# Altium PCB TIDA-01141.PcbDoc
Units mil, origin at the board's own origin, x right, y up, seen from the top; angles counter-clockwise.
Board outline 728.35 x 866.14 mil, 2 copper layers (Top Layer, Bottom Layer), stack 62 mil thick; 33 components, 14 nets, 69 pads, 28 vias.
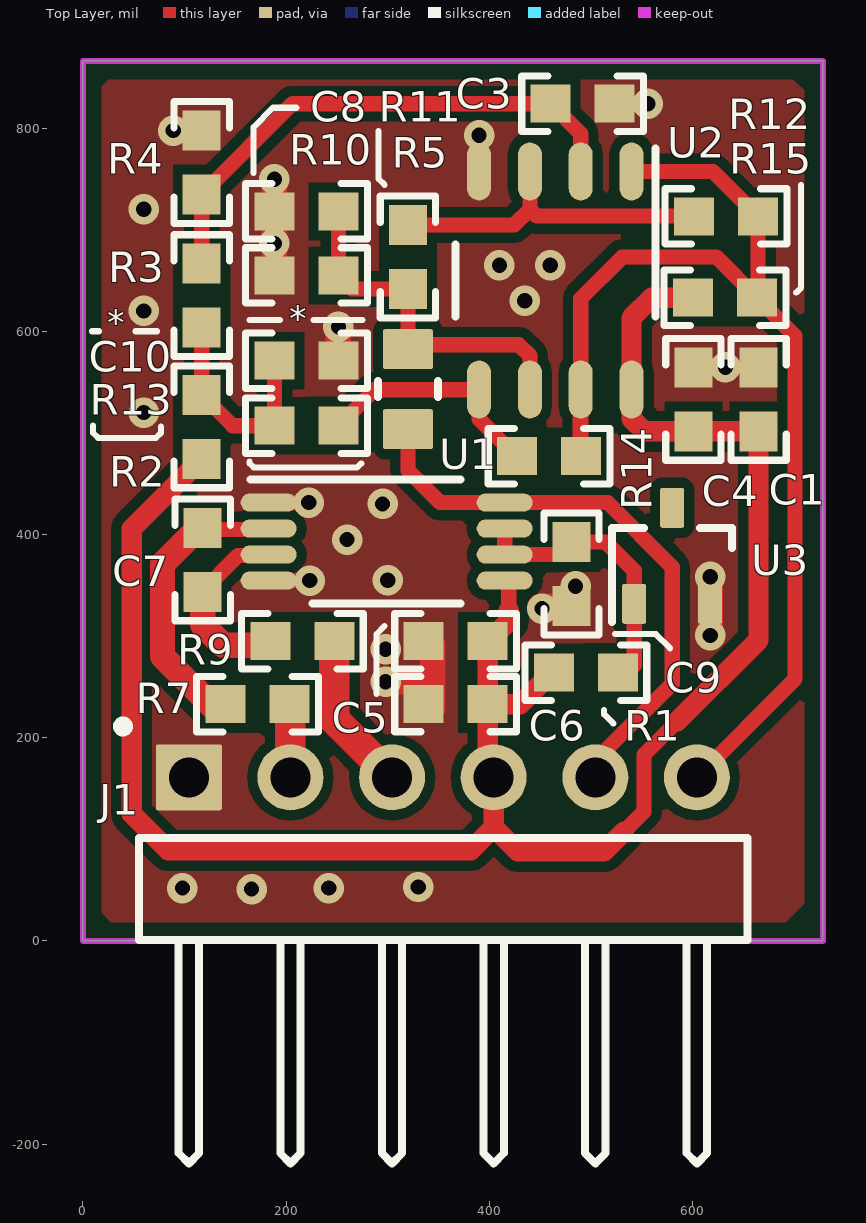
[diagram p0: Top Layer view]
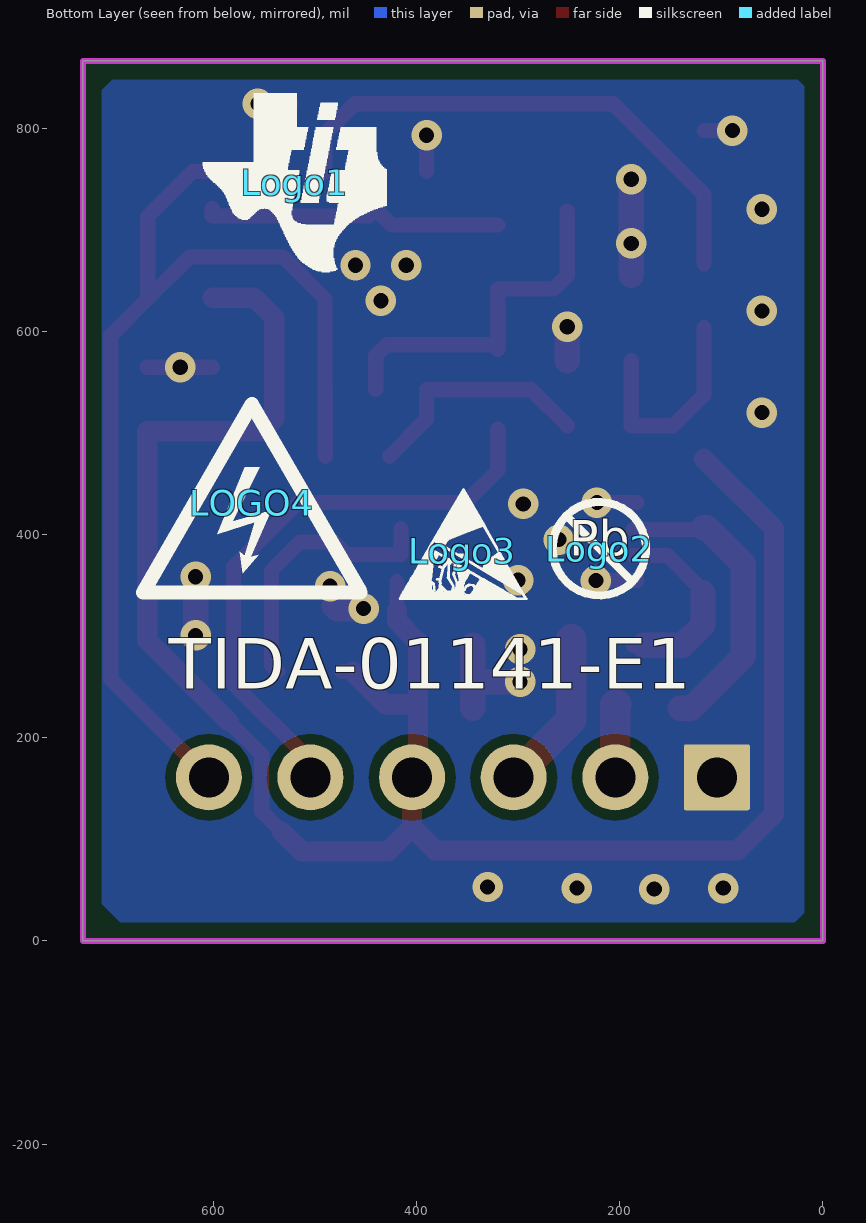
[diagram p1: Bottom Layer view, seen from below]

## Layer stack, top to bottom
Top Solder: solder mask 0.4, Solder Resist, Dk 3.5
Top Layer: signal copper 1.4
Dielectric1: core 59.2, FR-4 High Tg, Dk 4.8
Bottom Layer: signal copper 1.4
Bottom Solder: solder mask 0.4, Solder Resist, Dk 3.5

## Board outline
0,0 0,866.14 728.35,866.14 728.35,0

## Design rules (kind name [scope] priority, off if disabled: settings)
AcuteAngle [All] p1: minimum=4.50000000000000E+0001 checktracksonly=FALSE
AssemblyTestPointUsage [All] p1: valid=2
Clearance Clearance_Keepouts [((IsTrack Or IsArc) And Not InPoly) And IsFree and IsKeepOut vs ((IsTrack Or IsArc) And Not InPoly) And IsFree and IsKeepOut] p1: gap=15
Clearance Clearance_BoardEdge_MountingHoles [OnCopper and InComponentClass('Mounting Holes') vs IsKeepOut] p2: gap=40
Clearance Clearance_BoardEdge_Poly [OnCopper and InPoly vs IsKeepOut] p3: gap=15
Clearance Clearance_BoardEdge [OnCopper and Not InComponentClass('Logo') and not InComponentClass('FiducialMark') and not InRegion(1000,500,4000,800) and Not IsKeepout vs IsKeepOut] p4: gap=20 except(15: Track-Track)
Clearance Clearance_Poly [InPolygon] p5: gap=10
Clearance [All] p6: gap=7.87
ComponentClearance ComponentClearance_MountingHoles_FiducialMarks [InComponentClass('Mounting Holes') vs InComponentClass('FiducialMark')] p1: gap=50 collisioncheckmode=3 verticalgap=10 showdistances=FALSE
ComponentClearance ComponentClearance_Shunt [InComponentClass('Header') vs InComponentClass('Shunt')] p2: gap=0 collisioncheckmode=3 verticalgap=0 showdistances=FALSE
ComponentClearance ComponentClearance_Logo [InComponentClass('Logo')] p3: gap=50 collisioncheckmode=3 verticalgap=10 showdistances=FALSE
ComponentClearance ComponentClearance_ScrewToNut [(HasFootprint('NY PMS 440 0025 PH')) vs (HasFootprint('Keystone_1902C'))] p4: gap=5 collisioncheckmode=3 verticalgap=10 showdistances=FALSE
ComponentClearance ComponentClearance_MountingHoles [InComponentClass('Mounting Holes')] p5: gap=200 collisioncheckmode=3 verticalgap=100000 showdistances=FALSE
ComponentClearance ComponentClearance_SmallPassives [HasFootprint('0201*') or HasFootprint('0402*') or HasFootprint('0508') or HasFootprint('0603*') or HasFootprint('0612') or HasFootprint('0805*') or HasFootprint('0815*') or HasFootprint('0830*') or HasFootprint('1206*') or HasFootprint('1210*') or HasFootprint('1808*') or HasFootprint('1812*') or HasFootprint('1825*') or HasFootprint('2010*') or HasFootprint('2220*') or HasFootprint('2225*') or HasFootprint('2512*') or HasFootprint('2728*') or HasFootprint('3518*') vs HasFootprint('0201*') or HasFootprint('0402*') or HasFootprint('0508') or HasFootprint('0603*') or HasFootprint('0612') or HasFootprint('0805*') or HasFootprint('0815*') or HasFootprint('0830*') or HasFootprint('1206*') or HasFootprint('1210*') or HasFootprint('1808*') or HasFootprint('1812*') or HasFootprint('1825*') or HasFootprint('2010*') or HasFootprint('2220*') or HasFootprint('2225*') or HasFootprint('2512*') or HasFootprint('2728*') or HasFootprint('3518*')] p6: gap=20 collisioncheckmode=3 verticalgap=10 showdistances=FALSE
ComponentClearance ComponentClearance_THtoSMT [IsThruComponent vs IsSMTComponent] p7: gap=20 collisioncheckmode=3 verticalgap=20 showdistances=FALSE
ComponentClearance ComponentClearance_THtoTH [IsThruComponent vs IsThruComponent] p8: gap=10 collisioncheckmode=3 verticalgap=10 showdistances=FALSE
ComponentClearance [All] p9: gap=20 collisioncheckmode=3 verticalgap=10 showdistances=FALSE
DiffPairsRouting [All] p1: maxlimit=100 minlimit=10 mostfreqgap=10 toplayer_minwidth=15 toplayer_maxwidth=15 toplayer_prefwidth=15 bottomlayer_minwidth=15 bottomlayer_maxwidth=15 bottomlayer_prefwidth=15 maxuncoupledlength=1000
FabricationTestPointUsage TestPointUsage [All] p1: valid=2 allowmultiple=FALSE
FabricationTestpoint Testpoint [All] p1: side=3 testpointundercomponent=TRUE minsize=40 maxsize=100 preferedsize=60 minholesize=0 maxholesize=40 preferedholesize=32 testpointgrid=1 allowsidetop=TRUE allowsidebottom=TRUE usegrid=TRUE gridtolerance=0.01
FanoutControl Fanout_LCC [IsLCC] p1: bgadir=Out bgaviamode=Centered fanoutstyle=Auto fanoutdirection=Alternating viagrid=1 // Fanout_LCC (Default Rule)
FanoutControl Fanout_BGA [IsBGA] p2: bgadir=Out bgaviamode=Centered fanoutstyle=Auto fanoutdirection=Alternating viagrid=1 // Fanout_BGA (Default Rule)
FanoutControl Fanout_Default [All] p4: bgadir=Out bgaviamode=Centered fanoutstyle=Auto fanoutdirection=Alternating viagrid=1 // Fanout_Default (Default Rule)
FanoutControl Fanout_Small [(CompPinCount < 5)] p5: bgadir=Out bgaviamode=Centered fanoutstyle=Auto fanoutdirection=OutThenIn viagrid=1 // Fanout_Small (Default Rule)
HoleSize [All] p1: absolutevalues=TRUE maxlimit=251 minlimit=8 maxpercent=80.000 minpercent=20.000
MinimumAnnularRing MinimumAnnularRing_ThermalPadVias [IsVia and InAnyComponent] p1: minimumring=5.91
MinimumAnnularRing [All] p2: minimumring=6
MinimumSolderMaskSliver MinimumSolderMaskSliver_Logo [InComponentClass('Logo') vs InComponentClass('Logo')] p1: minsoldermaskwidth=0.7
MinimumSolderMaskSliver [All] p2: minsoldermaskwidth=3.94
PlaneConnect [All] p1: planeconnectstyle=Relief reliefexpansion=10 reliefentries=4 reliefconductorwidth=10 reliefairgap=10
PolygonConnect [All] p1: connectstyle=Direct reliefconductorwidth=10 reliefentries=4 polygonreliefangle="90 Angle" airgapwidth=10
RoutingVias ThermalPadVias [IsVia and InAnyComponent] p1: holewidth=7.87 width=19.68 viastyle="Through Hole" minholewidth=7.87 minwidth=19.68 maxholewidth=12.99 maxwidth=23.62
RoutingVias [All] p2: holewidth=12 width=24 viastyle="Through Hole" minholewidth=7.87 minwidth=26 maxholewidth=40 maxwidth=65
SilkToBoardRegionClearance [Not ((IsComment or IsDesignator) And (Hide <> 'False')) and not InRegion(1000,500,4000,800)] p1:
SilkToSilkClearance SilkToSilkClearance_Pb-FreeLogo [(HasFootprint('Pb-Free_Overlay_Medium') OR HasFootprint('Pb-Free_Overlay_Small')) vs (HasFootprint('Pb-Free_Overlay_Medium') OR HasFootprint('Pb-Free_Overlay_Small'))] p1: silktosilkclearance=0
SilkToSilkClearance [All] p2: silktosilkclearance=4
SilkToSolderMaskClearance "Silk to Solder Mask Opening" [All] p1: minsilkscreentomaskgap=4 clearancetoexposedcopper=FALSE
SolderMaskExpansion [All] p1: expansion=1.97
UnpouredPolygon [All] p1: allowunpoured=FALSE
Width [All] p1: maxlimit=60 minlimit=6 preferedwidth=20 checkconnectedcopper=TRUE
14 further rules are at their usual default settings.

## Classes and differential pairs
component class TIDA-01141_Sheet1: C1 C3 C4 C5 C6 C7 C8 C9 C10 J1 R1 R2 R3 R4 R5 R7 R9 R10 R11 R12 R13 R14 R15 U1 U2 U3
component class AssemblyNote: ZZ1 ZZ2 ZZ3
component class TIDA-01141_Hardware: Logo1 Logo2 Logo3 LOGO4 ZZ1 ZZ2 ZZ3
component class Logo: Logo1

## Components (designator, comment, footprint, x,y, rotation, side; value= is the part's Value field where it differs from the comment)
C1 "C0603C105K8PACTU" 0603 665,533 r270 top
C3 "06031C102JAT2A" 0603 492,824 r180 top
C4 "GRM188R71C104KA01D" 0603 601,533 r90 top
C5 "GRM188R71C104KA01D" 0603 367,295 r180 top
C6 "C0603C105K8PACTU" 0603 367,233 r0 top
C7 "06031C103JAT2A" 0603 118,375 r270 top
C8 "06031C102JAT2A" 0603 220,718 r0 top
C9 "06031C102JAT2A" 0603 481,361 r90 top
C10 "06031C102JAT2A" 0603 220,571 r180 top
J1 "TSW-106-08-G-S-RA" TSW-106-08-G-S-RA 354.33,161 r0 top locked
Logo1 "Texas Instruments" TI_Symbol_Overlay_Small 520,746 r180 bottom
Logo2 "Pb-Free Symbol" Pb-Free_Overlay_Small 220,386 r180 bottom
Logo3 "ESD Susceptible" ESD_Overlay_Small 355,384 r180 bottom
LOGO4 "DANGER HIGH VOLTAGE" IEC_HighVoltage_Small 562,431 r180 bottom
R1 "RC0603FR-075K11L" 0603 495,264 r180 top
R2 "CRCW060324K3FKEA" 0603 117,506 r270 top
R3 "CRCW060314K3FKEA" 0603 117,635 r270 top
R4 "CRCW06034K12FKEA" 0603 117,766 r270 top
R5 "CRCW08051K00FKEA" 0805_HV1 320,543 r90 top
R7 "CRCW06034R75FKEA" 0603 172,233 r180 top
R9 "CRCW06034R75FKEA" 0603 216,295 r180 top
R10 "CRCW06031K00FKEA" 0603 220,655 r180 top
R11 "CRCW060310K0FKEA" 0603 320,673 r90 top
R12 "CRCW06033M32FKEA" 0603 633,713 r0 top
R13 "CRCW060310K0FKEA" 0603 220,507 r180 top
R14 "CRCW06033M32FKEA" 0603 459,477 r0 top
R15 "CRCW06033K32FKEA" 0603 632,633 r180 top
U1 "INA240A2PW" PW0008A_N 299,393 r0 top
U2 "LM393AD" D0008A_N 465,650 r270 top
U3 "LM4040D30IDBZR" DBZ0003A_N 580,379 r90 top
ZZ1 "These assemblies are ESD sensitive, ESD precautions shall be observed." AssemblyNote -85,1683.6 r0 top
ZZ2 "These assemblies must be clean and free from flux and all contaminants. Use of no clean flux is not acceptable." AssemblyNote -85,1595.05 r0 top
ZZ3 "These assemblies must comply with workmanship standards IPC-A-610 Class 2, unless otherwise specified." AssemblyNote -85,1506.49 r0 top

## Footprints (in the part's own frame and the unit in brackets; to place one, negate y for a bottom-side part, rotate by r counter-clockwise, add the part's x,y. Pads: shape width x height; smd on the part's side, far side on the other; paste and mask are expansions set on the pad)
0603 [mm] "0603 from SM-752 data"
  rect 1x0.95 smd: 1(-0.8,0) 2(0.8,0)
  silkscreen extent -1.52,-0.69 1.52,0.69, body extent -0.87,-0.47 0.87,0.47, height 1
0805_HV1 [mm] "Custom footprint based on analyzing multiple manufacturer recommendations"
  rrect10% 1x1.25 smd: 1(-1,0) 2(1,0)
  silkscreen extent -0.2,-0.75 0.2,0.75, body extent -1.1,-0.72 1.1,0.73, height 1.45
AssemblyNote [mil] "Assembly Note"
D0008A_N [mm] "SOIC, 8-Leads, Body 4.9x3.9mm, Pitch 1.27mm, IPC Medium Density"
  oval 1.45x0.6 smd: 1(-2.725,1.905) 2(-2.725,0.635) 3(-2.725,-0.635) 4(-2.725,-1.905) 5(2.725,-1.905) 6(2.725,-0.635) 7(2.725,0.635) 8(2.725,1.905)
  silkscreen extent -3.3,-2.5 0.9,2.5, body extent -3,-2.45 3,2.45, height 1.63
DBZ0003A_N [mm] "SOT23, 3-Leads, Body 2.9x1.3mm, Pitch 0.95mm, Lead Span 2.4mm, IPC Medium Density"
  rrect17% 1x0.6 smd: 1(-1.2,0.95) 2(-1.2,-0.95) 3(1.2,0)
  silkscreen extent -1.65,-1.5 0.7,1.5, body extent -1.26,-1.46 1.26,1.46, height 0.98
ESD_Overlay_Small [mil]
  silkscreen extent -62,-48 64,61
IEC_HighVoltage_Small [mil]
  silkscreen extent -107,-88 107,97
Pb-Free_Overlay_Small [mil]
  silkscreen extent -46,-46 46,46
PW0008A_N [mm] "TSOP, 8-Leads, Body 3x4.4mm, Pitch 0.65mm, IPC Medium Density"
  oval 1.4x0.45 smd: 1(-2.95,0.975) 2(-2.95,0.325) 3(-2.95,-0.325) 4(-2.95,-0.975) 5(2.95,-0.975) 6(2.95,-0.325) 7(2.95,0.325) 8(2.95,0.975)
  silkscreen extent -3.4,-1.55 1.85,1.55, body extent -3.21,-1.5 3.21,1.5, height 1.2
TI_Symbol_Overlay_Small [mil]
  silkscreen extent -90,-88 91,88
TSW-106-08-G-S-RA [mm] "Samtec Right Angle Header"
  rrect6% 1.65x1.65 hole 1: 1(-6.35,0)
  round 1.65 hole 1: 2(-3.81,0) 3(-1.27,0) 4(1.27,0) 5(3.81,0) 6(6.35,0)
  silkscreen extent -8.12,-9.65 7.62,1.39, body extent -7.62,-9.91 7.62,0.32, height 3.05

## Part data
C1 C6: "CAP, CERM, 1 µF, 10 V, +/- 10%, X5R, 0603"
C3 C8 C9 C10: "CAP, CERM, 1000 pF, 100 V, +/- 5%, X7R, 0603"
C4 C5: "CAP, CERM, 0.1 µF, 16 V, +/- 10%, X7R, 0603"
C7: "CAP, CERM, 0.01 µF, 100 V, +/- 5%, X7R, 0603"
J1: "Header, 100mil, 6x1, Gold, R/A, TH"
Logo1: library part TI_Logo, "Texas Instrument Corporate Signature"
Logo2: library part Pb-Free
Logo3: library part ESD_Susceptible, "ESD Susceptible Symbol"
LOGO4: library part IEC_HighVoltage, "IEC 61010-1 High Voltage Warning"
R1: "RES, 5.11 k, 1%, 0.1 W, 0603"
R2: "RES, 24.3 k, 1%, 0.1 W, 0603"
R3: "RES, 14.3 k, 1%, 0.1 W, 0603"
R4: "RES, 4.12 k, 1%, 0.1 W, 0603"
R5: "RES, 1.00 k, 1%, 0.125 W, 0805"
R7 R9: "RES, 4.75, 1%, 0.1 W, 0603"
R10: "RES, 1.00 k, 1%, 0.1 W, 0603"
R11 R13: "RES, 10.0 k, 1%, 0.1 W, 0603"
R12 R14: "RES, 3.32 M, 1%, 0.1 W, 0603"
R15: "RES, 3.32 k, 1%, 0.1 W, 0603"
U1: "Wide Common-Mode Range, Voltage Output, High or Low-Side Bi-Directional Zero-Drift Current Shunt Monitor, PW0008A"
U2: "Dual Comparator, D0008A"
U3: "Precision Micropower Shunt Voltage Reference, 1% accuracy, 3 V, 15 ppm / degC, 15 mA, -40 to 85 degC, 3-pin SOT-23 (DBZ), Green (RoHS & no Sb/Br)"
ZZ1 ZZ2 ZZ3: library part AssemblyNote

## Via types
v1: diameter 30, hole 15, Top Layer to Bottom Layer, tented both sides, 28 vias

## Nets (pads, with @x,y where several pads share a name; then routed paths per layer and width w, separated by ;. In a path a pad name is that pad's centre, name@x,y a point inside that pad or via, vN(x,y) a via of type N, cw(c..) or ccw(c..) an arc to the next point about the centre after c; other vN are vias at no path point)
HTV: C10.2 R2.1 R3.2 R13.2 | length 214.1
  Top Layer w15: R3.2 R2.1 147.5,507 R13.2 C10.2
IBAT_ALERT: J1.6 R12.2 R14.2 R15.1 U2.1 U2.7 | length 1194.7
  Top Layer w15: U2.1@540,773 U2.1 620.21,757.28 R12.2 664.5,634 R15.1 ; J1.6 701,257.67 701,595.5 R15.1 ; U2.7 489.5,542.21 489.5,477 490,477.5 U2.7 ; U2.7 490,632 531,673 623.5,673 R15.1
IBAT_HS: J1.5 R5.1 U1.8 | length 578.3
  Top Layer w15: R5.1 320,463 351.61,431.39 U1.8 516.61,431.39 580,368 580,253 504.33,177.33 J1.5
IBAT_HS+: J1.2 R7.1 | length 72.3
  Top Layer w30: R7.1 204.33,232.17 J1.2
IBAT_HS-: J1.3 R9.1 | length 159.5
  Top Layer w30: R9.1@247.5,297 R9.1 247.5,217.83 J1.3
LTV: C3.2 R3.1 R4.2 U2.2 | length 527.5
  Top Layer w15: R3.1 R4.2 206.5,824 C3.2 490,794.5 U2.2
LV_AUX_3.3V: C1.2 C4.1 C5.1 C6.2 J1.4 R1.2 R2.2 R15.2 U1.5 U2.8 | length 1993.9
  Top Layer w15: 419.14,325 U1.5@419.14,353.61 ; R1.2@462.5,265 R1.2@473.5,265 ; 532.59,107.59 552.18,127.18 552.18,183.18 585,216
  Top Layer w20: R2.2 48,405.5 48,125 84,89 381.66,89 404.33,111.67 ; C5.1 C5.1@398.5,294 ; 419.13,325 419.13,314.63 C5.1@398.5,294 ; R1.2@462.5,265 430.5,233 C6.2 ; 532.59,107.59 513,88 428,88 404.33,111.67 ; 585,216 665,296 C1.2 C4.1 552.5,501.5 540,514 U2.8 540,613.12 559.88,633 R15.2 ; C6.2 398.5,166.83 J1.4 404.33,111.67 ; C6.2 C5.1@398.5,294
NetC7_1: C7.1 R7.2 U1.2 | length 371.6
  Top Layer w15: 78,291.5 78,355 ; C7.1 114,402.5 118,402.5 120.3,404.8 U1.2@186.86,404.8
  Top Layer w25: C7.1 113.79,406.5 78.37,371.08 78.37,280 129.37,229 R7.2@140.5,229
NetC7_2: C7.2 R9.2 U1.3 | length 195.4
  Top Layer w15: C7.2 118,342.5 117,343.5 152.7,379.2 U1.3@186.86,379.2 ; R9.2@176.5,291 R9.2@186.5,291
  Top Layer w25: C7.2@118,342.5 118,311 138,291 R9.2@176.5,291
NetC8_2: C8.2 R5.2 R10.1 R11.1 U2.6 | length 355.7
  Top Layer w15: C8.2 251.5,704 R10.1 264.99,641.5 R11.1 R5.2 324.26,586.63 429.37,586.63 440,576 U2.6
NetR11_2: R11.2 R12.1 U2.3 | length 334.6
  Top Layer w15: R11.2 424.5,704.5 440,720 ; U2.3 440,720 ; R12.1@601,720.5 601,713.37 446.63,713.37 440,720
NetR13_1: R13.1 R14.1 U2.5 | length 234.1
  Top Layer w15: R13.1 286.81,542.31 389.59,542.31 U2.5 390,513.5 R14.1@426.5,477
SGND: C1.1 C3.1 C4.2 C5.2 C6.1 C8.1 C9.1 C10.1 J1.1 R4.1 R10.2 U1.1 U1.4 U2.4 U3.2 | length 604.7
  Top Layer w15: v1@88.46,797 v1(88.95,797.5) R4.1 ; U1.4 v1(223.39,354.61) ; U1.1 v1(222.39,431.39) ; U2.4 v1(390,793) v1@390,796 ; C3.1 v1(556,824) ; C4.2 v1(632.5,564.5) C1.1
  Top Layer w25: R10.2 v1(188.5,686.5) C8.1 v1(188.5,749.5) ; C10.1 v1(251.5,604.5) ; v1(298,255) 339.5,255 344.5,260 ; C6.1@344.5,229 C5.2@344.5,291 ; v1(617.4,300.6) U3.2 v1(617.4,358.4) ; v1@450.07,328.93 v1(452,327) 478.5,327 C9.1 450.07,329.5 v1@450.07,328.93
  other v1: 166,51 98,52 242,52 330,53 298,287 485,349 300,355 260,395 295,430 60,520 60,620 435,630 410,665 460,665 60,720
VREF: C9.2 R1.1 U1.6 U1.7 U3.1 | length 271.7
  Top Layer w15: U1.7 U1.6 468.71,380.2 C9.2 514.5,392.5 542.6,364.4 U3.1 542.6,271.1 R1.1@536.5,265
pads on no net: U3.3

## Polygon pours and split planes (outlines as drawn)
SGND on Top Layer "M9 Title Sheet-No Net" (solid, remove dead copper, pour order 4): 0,806 0,46 46,0 673.35,0 728.35,55 728.35,818.65 679,868 45,868 0,823
SGND on Bottom Layer "M9 Title Sheet-No Net" (solid, remove dead copper, pour order 3): 0,806 0,46 46,0 673.35,0 728.35,55 728.35,818.65 679,868 45,868 0,823

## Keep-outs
Keep-Out Layer:
  lines w6: 0,0 728.35,0 728.35,866.14 0,866.14 0,0 ; 708.66,0 708.66,0
  lines w10: 4730,3149.49 cw(c4730,3144.49) 4735,3144.49 ccw(c4730,3144.49) 4730,3149.49
  text ".Layer_Name" at 357,-1164.01 h60

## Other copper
Top Layer:
  text ".Layer_Name" at 357,-1164.01 h60
Bottom Layer:
  text ".Layer_Name" at 357,-1164.01 h60

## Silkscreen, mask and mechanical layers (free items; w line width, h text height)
Top Overlay:
  lines w6: 9,600 16,600 ; 10,507 10,500 15,495 72,495 77,500 77,506 ; 52,600 73,600 ; 164,472 164,470 168,466 270,466 274,470 ; 164,611 194,611 ; 168,756 168,801 187,820 210,820 ; 227,611 275,611 ; 289,243 289,302 297,310 ; 291,797 291,750 297,744 ; 513,227 513,223 522,214 ; 524,302 564,302 578,288 ; 702,638 707,643 707,744
  text "*" at 203,600 h25
  text "*" at 24,596 h25
  text ".Layer_Name" at 357,-1164.01 h60
Bottom Overlay:
  text "TIDA-01141-E1" at 644,248 h50
  text ".Layer_Name" at 357,-1164.01 h60
Top Paste:
  text ".Layer_Name" at 357,-1164.01 h60
Bottom Paste:
  text ".Layer_Name" at 357,-1164.01 h60
Top Solder:
  text ".Layer_Name" at 357,-1164.01 h60
  text ".Layer_Name" at 357,-1164.01 h60
Bottom Solder:
  text ".Layer_Name" at 357,-1164.01 h60
Drill Guide:
  text ".Layer_Name" at 357,-1164.01 h60
M1 Board Outline:
  the board outline again, w10
M2 Board Dimensions:
  rectangle: -95,-705.51 280,-580.51
  rectangle: -220,-580.51 -95,-455.51
  lines w7: -220,-580.51 780,-580.51 ; -95,-705.51 -95,-455.51 ; 30,-705.51 30,-455.51 ; 280,-705.51 280,-455.51 ; 530,-705.51 530,-455.51 ; -220,-705.51 -220,-455.51 780,-455.51 780,-705.51 -220,-705.51
M3 3D STEP Top:
  text ".Layer_Name" at 357,-1164.01 h60
M4 3D STEP Bottom:
  text ".Layer_Name" at 357,-1164.01 h60
M5 Assembly Top:
  lines w10: -512,-1235.68 6088,-1235.68 ; -512,-1032.35 6090,-1032.35 ; -512,-829.01 -512,-1439.01 3493,-1439.01 6090,-1439.01 6090,-829.01 -511.5,-829.01 -511.5,-1439.01 1064,-1439.01 ; 1953,-1439.01 1953,-829.01 ; 3220,-1032.35 3220,-829.01 ; 4060,-1032.35 4060,-829.01 ; 4682,-1445.51 4682,-1242.68
  text "COMPONENTS MARKED 'DNP' SHOULD NOT BE POPULATED." at 933.5,-624.01 h60
  text "ASSEMBLY VARIANT:" at 933,-739.51 h60
  text ".VariantName" at 1969,-739.51 h60
  text "PCB VIEWED FROM TOP SIDE" at -448.5,-961.18 h60
  text "BOARD #:" at 2028,-961.18 h60
  text ".PRJ_Number" at 2573.5,-961.18 h60
  text "REV:" at 3418,-961.18 h60
  text ".PCB_Rev" at 3709.5,-961.18 h60
  text "SVN REV:" at 4256,-961.18 h60
  text ".VersionControl_RevNumber" at 4762,-961.18 h60
  text ".LAyer_Name" at 317,-1163 h60
  text "TID #:" at 2028,-1164.51 h60
  text ".TID" at 2573.5,-1164.51 h60
  text "PLOT NAME =" at -448.5,-1369.85 h60
  text ".plot_File_Name" at 357,-1369.85 h60
  text "GENERATED    :" at 2030,-1369.85 h60
  text ".Print_Date" at 2899.5,-1369.85 h60
  text ".Print_Time" at 3628.5,-1369.85 h60
  text "TEXAS INSTRUMENTS" at 4893,-1369.85 h60
M6 Assembly Bottom:
  lines w10: -512.5,-1032.85 6089.5,-1032.85 ; -510.5,-1236.18 6089.5,-1236.18 ; 895.5,-1446.01 895.5,-1243.18 ; 1517.5,-1032.85 1517.5,-829.51 ; 2357.5,-1032.85 2357.5,-829.51 ; 3624.5,-1439.51 3624.5,-829.51 ; 4513.5,-1439.51 6089,-1439.51 6089,-829.51 -512.5,-829.51 -512.5,-1439.51 2084.5,-1439.51 6089.5,-1439.51 6089.5,-829.51
  text "COMPONENTS MARKED 'DNP' SHOULD NOT BE POPULATED." at 5882,-623.51 h60
  text ".VariantName" at 4838,-739.51 h60
  text "ASSEMBLY VARIANT:" at 5877,-739.51 h60
  text ".VersionControl_RevNumber" at 815.5,-961.68 h60
  text "SVN REV:" at 1321.5,-961.68 h60
  text ".PCB_Rev" at 1868,-961.68 h60
  text "REV:" at 2159.5,-961.68 h60
  text ".PRJ_Number" at 3004,-961.68 h60
  text "BOARD #:" at 3549.5,-961.68 h60
  text "PCB VIEWED FROM BOTTOM SIDE" at 6026,-961.68 h60
  text ".LAyer_Name" at 5043,-1160 h60
  text ".TID" at 3004,-1165.01 h60
  text "TID #:" at 3549.5,-1165.01 h60
  text "TEXAS INSTRUMENTS" at 684.5,-1370.35 h60
  text ".Print_Time" at 1949,-1370.35 h60
  text ".Print_Date" at 2678,-1370.35 h60
  text "GENERATED    :" at 3547.5,-1370.35 h60
  text ".plot_File_Name" at 5220.5,-1370.35 h60
  text "PLOT NAME =" at 6026,-1370.35 h60
M9 Title Sheet:
  drawing of 57 lines, arcs and shapes, not listed
  text "1" at 519.84,7730.99 h70
  text "2" at 3015.5,7730.99 h70
  text "3" at 5504.84,7730.99 h70
  text "4" at 8011.51,7730.99 h70
  text "5" at 10510.5,7730.99 h70
  text "6" at 13015.5,7730.99 h70
  text "A" at -636.5,6587.99 h70
  text "A" at 14163.5,6587.99 h70
  text "B" at -636.5,4207.99 h70
  text "B" at 14163.5,4207.99 h70
  text "C" at -636.5,1832.99 h70
  text "C" at 14163.5,1832.99 h70
  text "PROJECT TITLE:" at 11123.5,-28.01 h45
  text ".PRJ_Title" at 11173.5,-161.34 h70
  text "DESIGNED FOR:" at 11123.5,-329.01 h45
  text ".PRJ_Customer" at 11173.5,-469.01 h70
  text "D" at -636.5,-537.01 h70
  text "D" at 14163.5,-537.01 h70
  text "FILE NAME:" at 11123.5,-629.01 h45
  text ".PCB_File_Name_No_Path" at 11173.5,-749.01 h70
  text "Texas Instruments (TI) and/or its licensors do not warrant the accuracy or completeness of this specification" at 6154,-910.85 h45
  text "ENGINEER:" at 11123.5,-919.01 h45
  text "LAYOUT BY:" at 12628.5,-919.01 h45
  text "or any information contained therein. TI and/or its licensors do not warrant that this design will meet" at 6109.01,-1023.52 h45
  text ".PRJ_Engineer" at 11173.5,-1074 h70
  text ".PCB_Layout" at 12679,-1074 h70
  text "the specifications, will be suitable for your application or fit for any particular purpose, or will operate in" at 6109.01,-1136.18 h45
  text "ALTIUM DESIGNER VERSION:" at 12628.5,-1229.01 h45
  text "an implementation. TI and/or its licensors do not warrant that the design is production worthy. You should" at 6109.01,-1248.85 h45
  text "completely validate and test your design implementation to confirm the system functionality for your application." at 6154,-1361.51 h45
  text ".print_Scale" at 11173.5,-1362.34 h70
  text ".Application_BuildNumber" at 12679,-1362.34 h70
  text "1" at 519.84,-1569.01 h70
  text "2" at 3015.5,-1569.01 h70
  text "3" at 5504.84,-1569.01 h70
  text "4" at 8011.51,-1569.01 h70
  text "5" at 10510.5,-1569.01 h70
  text "6" at 13015.5,-1569.01 h70
M10 Fab Notes:
  drawing of 191 lines, arcs and shapes, not listed
  text "DESIGN INFORMATION" at 12166.52,6384.49 h60
  text "(REFER ALSO ARRAY/PANEL PROFILING INFORMATION)" at 11804.96,6222.77 h60
  text "BOARD SIZE" at 11118.96,6218.49 h60
  text "X" at 12086.96,6090.67 h60
  text "22MM" at 12322.5,6083.49 h60
  text "18.5MM" at 11581,6080 h60
  text "Number of Layers :" at 11536.96,5983.49 h60
  text "2" at 12631.77,5973.49 h60
  text "MIN. TRACK WIDTH:" at 11536.96,5844.49 h60
  text "15" at 12606.5,5844.89 h60
  text "MIL" at 12787.96,5844.49 h60
  text "MIN. CLEARANCE:" at 11536.96,5712.49 h60
  text "7.874" at 12475,5709 h60
  text "MIL" at 12805.5,5685.89 h60
  text "MIN. VIA PAD SIZE:" at 11536.96,5580.49 h60
  text "30" at 12617.5,5580.89 h60
  text "MIL" at 12805.5,5557.89 h60
  text "0.19mm (7.5MIL)" at 12231.96,5438.78 h60
  text "EXTERNAL" at 12968.5,5438.89 h60
  text "MINIMUM ANNULAR RING" at 11207.73,5434.49 h60
  text "PER" at 11407.73,5316.49 h60
  text "IPC-D-275 CLASS 2 LEVEL C" at 11627.73,5316.49 h60
  text "MIL, HOLES" at 13115.96,5204.2 h60
  text "+/-" at 12723.5,5203.49 h60
  text "+/-" at 13577.5,5203.49 h60
  text "REGISTRATION TOLERANCES:" at 11207.73,5198.49 h60
  text "METAL" at 12407.5,5198.49 h60
  text "5" at 12983.7,5198.49 h60
  text "3" at 13816.7,5198.49 h60
  text "MIL" at 13932.96,5198.49 h60
  text "IMPEDENCE CONTROLLED BOARD:NO" at 11240.5,5049.49 h60
  text "MATERIAL:" at 11116.96,4826.03 h60
  text "FR-4 High Tg" at 12103.4,4685.7 h60
  text "FR-408" at 11537.96,4677.13 h60
  text "OTHER" at 13025.96,4677.13 h60
  text "X" at 11941.5,4675.49 h60
  text "THICKNESS:" at 11118.5,4520.49 h60
  text "63 MIL (1.6mm) +/-10%" at 11777.5,4515.49 h60
  text "OTHER" at 13142.96,4510.13 h60
  text "X" at 11642.5,4507.49 h60
  text "TOLERANCE:" at 11191.73,4352.13 h60
  text "X" at 12031.03,4352.13 h60
  text "ANSI IPC-6012 TYPE 3 CLASS 2" at 12217.98,4352.13 h60
  text "OTHER +/-" at 12217.96,4196.13 h60
  text "BOW & TWIST:" at 11191.73,4039.13 h60
  text "X" at 12031.03,4039.13 h60
  text "ANSI IPC-6012 TYPE 3 CLASS 2" at 12217.98,4039.13 h60
  text "OTHER +/-" at 12217.96,3880.62 h60
  text "DRILLING:" at 11116.96,3742.13 h60
  text "REFERENCE:" at 11191.73,3625.13 h60
  text "X" at 11839.96,3625.13 h60
  text "AS SHOWN" at 12026.96,3625.13 h60
  text "X" at 12740.96,3625.13 h60
  text "NC_DRILL FILES" at 12877.96,3625.13 h60
  text "PTH MIN COPPER THICKNESS:" at 11191.73,3467.13 h60
  text "X" at 12541.96,3467.13 h60
  text "1MIL" at 12678.96,3467.13 h60
  text "OTHER" at 13175.96,3467.13 h60
  text "BOARD FINISH:" at 11116.96,3308.13 h60
  text "SILKSCREEN:" at 11272.18,3190.13 h60
  text "X" at 12220.96,3190.13 h60
  text "TOP" at 12346.96,3190.13 h60
  text "X" at 12730.96,3190.13 h60
  text "BOTTOM" at 12857.96,3190.13 h60
  text "SILKSCREEN COLOR:" at 11272.18,3023.13 h60
  text "X" at 12219.92,3023.13 h60
  text "WHITE" at 12346.96,3023.13 h60
  text "OTHER" at 12857.96,3023.13 h60
  text "SOLDER RESIST COLOR:" at 11272.18,2853.13 h60
  text "X" at 11839.92,2693.93 h60
  text "GREEN" at 11966.96,2693.93 h60
  text "BLUE" at 12557.96,2693.93 h60
  text "OTHER" at 13095.96,2693.93 h60
  text "IMMERSION GOLD (ENIG)" at 12177.96,2505.41 h60
  text "ENEPIG" at 13515.5,2502.13 h60
  text "SURFACE FINISH:" at 11116.96,2501.13 h60
  text "X" at 11991.01,2501.13 h60
  text "IMM. TIN/SILVER OR EQUIV" at 11446.5,2344.13 h60
  text "OTHER" at 12877.96,2344.13 h60
  text "ARRAY/PANEL:" at 11116.96,2165.13 h60
  text "CUT AND TRIM PER MECH LAYER 1" at 12177.96,2160.84 h60
  text "N.C. ROUTE" at 12177.96,2009.13 h60
  text "X" at 12856.96,2009.13 h60
  text "V. SCORE" at 13043.96,2009.13 h60
  text "CERTIFICATION:" at 11116.96,1872.13 h60
  text "MATERIALS AND WORKMANSHIP FOR ALL PCBS" at 11841.96,1872.13 h60
  text "TO MEET OR EXCEED THE REQUIREMENTS OF:" at 11841.96,1774.13 h60
  text "X" at 11468.46,1637.62 h60
  text "ANSI IPC-A-600F CLASS ->" at 11607.46,1637.62 h60
  text "X" at 13246.52,1637.62 h60
  text "2" at 13365.46,1637.62 h60
  text "1" at 13050.46,1636.13 h60
  text "3" at 13719.46,1636.13 h60
  text "X" at 11470.52,1478.13 h60
  text "UL 94V-0" at 11607.46,1478.13 h60
  text "X" at 12282.52,1478.13 h60
  text "RoHS" at 12419.46,1478.13 h60
  text "OTHER" at 13063.86,1478.13 h60
  text "PER ORDER" at 13460.92,1478.13 h60
  text "ADDITIONAL REQUIREMENTS:" at 11116.96,1337.13 h60
  text "MICROSECTION:" at 11191.73,1222.13 h60
  text "YES" at 12097.46,1222.13 h60
  text "REQUIRED" at 12958.96,1065.98 h60
  text "BARE BOARD ELEC. TEST:" at 11191.73,1063.13 h60
  text "NONE" at 12497.46,1063.13 h60
  text "X" at 12831.96,1063.13 h60
  text "PER ORDER" at 13550.96,1063.13 h60
  text "MANUFACTURER'S UL:" at 11191.73,906.13 h60
  text "RAIL" at 12357.46,901.84 h60
  text "METAL" at 12849.27,901.84 h60
  text "X" at 13224.5,901.49 h60
  text "SILK" at 13360.96,901.84 h60
  text "VIA`S TO BE TENTED:" at 11171.5,714.49 h60
  text "YES" at 12076.5,714.49 h60
M11 Gerber Information:
  lines w10: -512,-1235.68 6088,-1235.68 ; -512,-1032.35 6090,-1032.35 ; -512,-829.01 -512,-1439.01 3493,-1439.01 6090,-1439.01 6090,-829.01 -511.5,-829.01 -511.5,-1439.01 1064,-1439.01 ; 1953,-1439.01 1953,-829.01 ; 3220,-1032.35 3220,-829.01 ; 4060,-1032.35 4060,-829.01 ; 4682,-1445.51 4682,-1242.68
  text "ALL ARTWORK VIEWED FROM TOP SIDE" at -448.5,-961.18 h60
  text "BOARD #:" at 2028,-961.18 h60
  text ".PRJ_Number" at 2573.5,-961.18 h60
  text "REV:" at 3418,-961.18 h60
  text ".PCB_Rev" at 3709.5,-961.18 h60
  text "SVN REV:" at 4256,-961.18 h60
  text ".VersionControl_RevNumber" at 4762,-961.18 h60
  text "LAYER NAME =" at -448.5,-1164.01 h60
  text "TID #:" at 2028,-1164.51 h60
  text ".TID" at 2573.5,-1164.51 h60
  text "PLOT NAME =" at -448.5,-1369.85 h60
  text ".plot_File_Name" at 357,-1369.85 h60
  text "GENERATED    :" at 2030,-1369.85 h60
  text ".Print_Date" at 2899.5,-1369.85 h60
  text ".Print_Time" at 3628.5,-1369.85 h60
  text "TEXAS INSTRUMENTS" at 4893,-1369.85 h60
M12 Stackup:
  drawing of 191 lines, arcs and shapes, not listed
  text "Layer" at 9441,7451 h60
  text "Name" at 9850.91,7451 h60
  text "Material" at 10780.66,7451 h60
  text "Thickness" at 11640.42,7451 h60
  text "Constant" at 12290.26,7451 h60
  text "Board Layer Stack" at 12860.12,7451 h60
  text "1" at 9441,7331 h60
  text "Top Overlay" at 9850.91,7331 h60
  text "2" at 9441,7211 h60
  text "Top Solder" at 9850.91,7211 h60
  text "Solder Resist" at 10780.66,7211 h60
  text "0.40mil" at 11640.42,7211 h60
  text "3.5" at 12290.26,7211 h60
  text "3" at 9441,7091 h60
  text "Top Layer" at 9850.91,7091 h60
  text "Copper" at 10780.66,7091 h60
  text "1.40mil" at 11640.42,7091 h60
  text "4" at 9441,6971 h60
  text "Dielectric1" at 9850.91,6971 h60
  text "FR-4 High Tg" at 10780.66,6971 h60
  text "59.20mil" at 11640.42,6971 h60
  text "4.8" at 12290.26,6971 h60
  text "5" at 9441,6851 h60
  text "Bottom Layer" at 9850.91,6851 h60
  text "Copper" at 10780.66,6851 h60
  text "1.40mil" at 11640.42,6851 h60
  text "6" at 9441,6731 h60
  text "Bottom Solder" at 9850.91,6731 h60
  text "Solder Resist" at 10780.66,6731 h60
  text "0.40mil" at 11640.42,6731 h60
  text "3.5" at 12290.26,6731 h60
  text "7" at 9441,6611 h60
  text "Bottom Overlay" at 9850.91,6611 h60
M13 Component Bodies Top:
  text ".Layer_Name" at 357,-1164.01 h60
M14 Component Bodies Bottom:
  text ".Layer_Name" at 357,-1164.01 h60
M15 Courtyards Top:
  text ".Layer_Name" at 357,-1164.01 h60
M16 Courtyards Bottom:
  text ".Layer_Name" at 357,-1164.01 h60
Drill Drawing:
  circle w4: c3536.12,842 r25
  lines w4: 3511.12,667 3561.12,667 3561.12,717 3511.12,717 3511.12,667
  lines w15: 3443,622 7321.97,622 ; 3443,922 7321.97,922 ; 3993.88,472 3993.88,1072 ; 4691.69,472 4691.69,1072 ; 6037.29,472 6037.29,1072 ; 6543.17,472 6543.17,1072 ; 3443,472 7321.97,472 7321.97,1072 3443,1072 3443,472
  text "Symbol" at 3533,967 h72
  text "Hit Count" at 4038.88,967 h72
  text "Finished Hole Size" at 4736.69,967 h72
  text "Plated" at 6082.29,967 h72
  text "Hole Type" at 6588.17,967 h72
  text "6" at 4038.88,817 h60
  text "39.37mil (1.000mm)" at 4736.69,817 h60
  text "PTH" at 6082.29,817 h60
  text "Round" at 6588.17,817 h60
  text "28" at 4038.88,667 h60
  text "15.00mil (0.381mm)" at 4736.69,667 h60
  text "PTH" at 6082.29,667 h60
  text "Round" at 6588.17,667 h60
  text "34 Total" at 4038.88,517 h60
  text "DRILL TABLE" at 3525,299 h60
  text "FOR PTH +3/-3MIL" at 3525,192 h60
  text "This is not impedence controlled board." at 3511,85 h60
  text ".Layer_Name" at 357,-1164.01 h60

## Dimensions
-220,-705.51 to 780,-705.51 on M2 Board Dimensions
0,0 to 728.35,0 on M2 Board Dimensions
0,0 to 0,866.14 on M2 Board Dimensions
